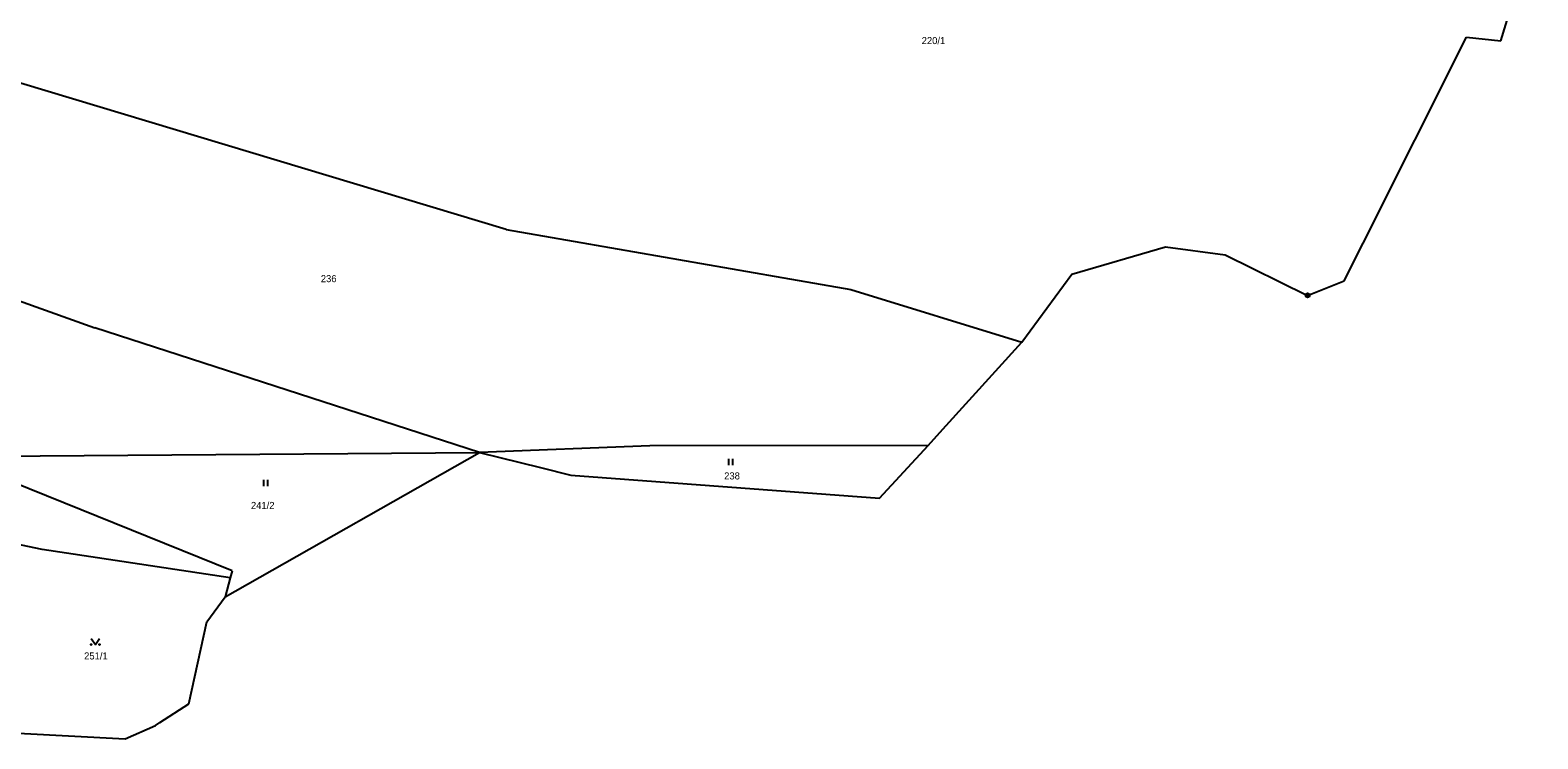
# Model space of a CAD drawing. Extents: x -645290 to -643454, y -1064771 to -1062356.
# Drawn here: x -643880.7 to -643517.1, y -1063540.7 to -1063369.7 of the extents above; entities that cross this region are included whole.
import ezdxf

# ---------------------------------------------------------------- set-up
doc = ezdxf.new("R2010")
doc.units = 0
doc.header["$LTSCALE"] = 0.68
for name, color, linetype, lineweight in [('1', 7, 'Continuous', 25), ('3', 7, 'Continuous', 25), ('8', 7, 'Continuous', 25)]:
    doc.layers.add(name, color=color, linetype=linetype, lineweight=lineweight)
doc.layers.add('2', color=7, linetype='Continuous')

msp = doc.modelspace()

# ---------------------------------------------------------------- linework, layer by layer
at = {"layer": '1'}
for p, q in [((-643526.05, -1063372.26), (-643517.11, -1063343.41)), ((-643765.92, -1063417.81), (-643911.48, -1063373.94)), ((-643559.27, -1063421.09), (-643534.3, -1063371.4)), ((-643534.3, -1063371.4), (-643526.05, -1063372.26)), ((-643973.12, -1063402.76), (-643865.15, -1063441.55)), ((-643765.92, -1063417.81), (-643682.8, -1063432.3)), ((-643563.82, -1063430.14), (-643559.27, -1063421.09)), ((-643629.51, -1063428.55), (-643606.89, -1063421.96)), ((-643606.89, -1063421.96), (-643592.55, -1063423.93)), ((-643592.55, -1063423.93), (-643572.63, -1063433.68)), ((-643641.56, -1063444.98), (-643629.51, -1063428.55)), ((-643682.8, -1063432.3), (-643641.56, -1063444.98)), ((-643572.63, -1063433.68), (-643563.82, -1063430.14)), ((-643772.34, -1063471.61), (-643865.15, -1063441.55)), ((-643660.64, -1063465.99), (-643641.56, -1063444.98)), ((-643664.19, -1063469.91), (-643660.64, -1063465.99)), ((-643900.36, -1063472.59), (-643772.34, -1063471.61)), ((-643831.3, -1063505.03), (-643772.34, -1063471.61)), ((-643731.31, -1063470), (-643772.34, -1063471.61)), ((-643772.34, -1063471.61), (-643757.69, -1063475.22)), ((-643664.19, -1063469.91), (-643731.31, -1063470)), ((-643675.88, -1063482.63), (-643664.19, -1063469.91)), ((-643832.05, -1063500.16), (-643900.36, -1063472.59)), ((-643757.69, -1063475.22), (-643750.35, -1063477.03)), ((-643750.35, -1063477.03), (-643675.88, -1063482.63)), ((-643877.87, -1063494.98), (-643889.39, -1063492.58)), ((-643832.54, -1063501.82), (-643877.87, -1063494.98)), ((-643832.05, -1063500.16), (-643832.54, -1063501.82)), ((-643832.54, -1063501.82), (-643833.69, -1063506.39)), ((-643833.69, -1063506.39), (-643831.3, -1063505.03)), ((-643838.15, -1063512.45), (-643833.69, -1063506.39)), ((-643842.47, -1063532.2), (-643838.15, -1063512.45)), ((-643849.43, -1063536.76), (-643842.47, -1063532.2)), ((-643857.86, -1063540.68), (-643850.54, -1063537.49)), ((-643850.54, -1063537.49), (-643849.43, -1063536.76)), ((-643883.62, -1063539.27), (-643857.86, -1063540.68))]:
    msp.add_line(p, q, dxfattribs=at)
at = {"layer": '3'}
for p, q in [((-643712.241, -1063474.65), (-643712.241, -1063473.15)), ((-643711.24, -1063474.65), (-643711.24, -1063473.15)), ((-643824.391, -1063479.72), (-643824.391, -1063478.22)), ((-643823.39, -1063479.72), (-643823.39, -1063478.22))]:
    msp.add_line(p, q, dxfattribs=at)
msp.add_lwpolyline([(-643866, -1063516.439), (-643865, -1063517.94), (-643864, -1063516.439)], dxfattribs=at)
for centre in [(-643866, -1063517.9395), (-643864, -1063517.9395)]:
    msp.add_circle(centre, 0.1, dxfattribs=at)
at = {"layer": '8'}
for radius in [0.5, 0.0303]:
    msp.add_circle((-643572.63, -1063433.6799), radius, dxfattribs=at)

# ---------------------------------------------------------------- texts
at = {"layer": '2'}
for s, p in [('220/1', (-643665.72, -1063373.074)), ('236', (-643810.64, -1063430.505)), ('238', (-643713.36, -1063478.094)), ('241/2', (-643827.49, -1063485.215)), ('251/1', (-643867.73, -1063521.525))]:
    msp.add_text(s, height=1.7, dxfattribs=at).set_placement(p)

doc.saveas('drawing.dxf')
